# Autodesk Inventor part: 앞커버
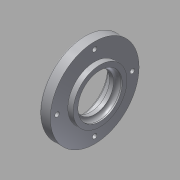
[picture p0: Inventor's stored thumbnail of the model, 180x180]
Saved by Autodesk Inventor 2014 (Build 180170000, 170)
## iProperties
Created: 2015-09
Part Number: 앞커버
Material: 알루미늄 6061
Document SubType Name: Modeling
Designer: mduedu
Density: 2.71 g/cm^3
Mass: 58.9874 g
Surface Area: 98.7754 cm^2
Volume: 21.7666 cm^3
Appearance: Aluminum - Flat
Author: mduedu
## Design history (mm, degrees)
sketch "스케치1"
  geometry: L1 (-8, 67)-(-12, 67); L2 (-12, 67)-(-12, 80); L3 (-12, 80)-(-20, 80); L4 (-20, 80)-(-20, 70.5); L5 (-23, 70.5)-(-23, 61); L6 (-23, 61)-(-8, 61); L7 (-8, 61)-(-8, 67); L8 (-79.5, 39.5)-(-79.5, 54.5) reference; L9 (48.5, 54.5)-(48.5, 39.5) reference; L10 (-79.5, 47)-(48.5, 47); L11 (-20, 70.5)-(-23, 70.5); 3 further points
  constraints: 18 end point, 6 parallel, 4 midpoint, 1 horizontal, 1 perpendicular, 1 vertical alignment
  dimensions: "d0" = 15 distance between parallel lines of L7 L5; "d2" = 28 diameter of L6 L10; "d3" = 40 diameter of L1 L10; "d5" = 4 distance of L1.start L1.end; "d6" = 66 diameter of L3 L10; "d7" = 8 distance of L2.end L3.end; "d8" = 47 diameter of L4.end L10
revolve "회전1" sketch "스케치1" stored, may be unused: angle "d4" = 90 deg
sketch "스케치2"
  geometry: C1 r 33 at (0, 0) reference; 2 further points
  constraints: 1 coincident
hole "구멍1" sketch "스케치2" at (0, 0) diameter "d11" = 33; stored, may be unused: countersink angle "d15" = 90 deg, drill point angle "d17" = 0 deg; dims "d12" = 6, "d13" = 4, "d14" = 2, "d16" = 4
fillet "모깎기1" dims "d18" = 3
fillet "모깎기2" dims "d19" = 1
sketch "스케치3"
  geometry: C1 r 33 at (0, 0) reference; 2 further points
  constraints: 1 coincident
hole "구멍2" sketch "스케치3" at (0, 0) diameter "d20" = 40; stored, may be unused: countersink angle "d24" = 90 deg, drill point angle "d26" = 0 deg; dims "d21" = 6, "d22" = 4, "d23" = 2, "d25" = 8
fillet "모깎기3" dims "d27" = 0.4
chamfer "모따기1" distance "d28" = 1; stored, may be unused: second distance "d29" = 2, angle "d30" = 30 deg
sketch "스케치4" dims "d31" = 56
  geometry: C1 r 33 at (0, 0) reference; 6 further points
  constraints: 2 vertical alignment, 1 coincident, 7 other
  dimensions: "d36" = 360 deg dimension on C1.centre point (0, 28) (derived)
sketch "스케치7"
  geometry: 4 further points
hole "구멍4" sketch "스케치7" at (0, 28), (-28, 0), (28, 0), (0, -28) diameter "d48" = 3.4; stored, may be unused: countersink angle "d52" = 90 deg, drill point angle "d54" = 0 deg; dims "d49" = 6, "d50" = 6.5, "d51" = 3.4, "d53" = 8
node "솔리드1"
node "참조1"
node "참조2"
